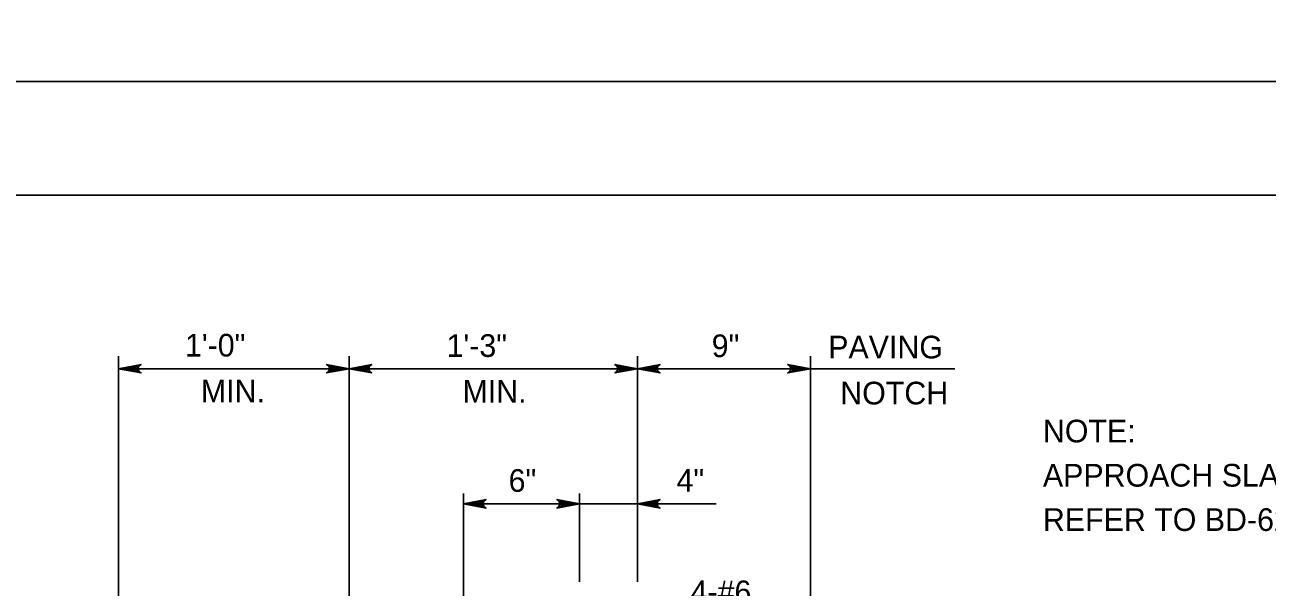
# Model space of a CAD drawing. Extents: x 638653 to 642302, y 298557 to 300414.
# Drawn here: x 639135.8 to 639300, y 299083.7 to 299158 of the extents above; entities that cross this region are included whole.
import ezdxf

# ---------------------------------------------------------------- set-up
doc = ezdxf.new("R2010")
doc.units = 0
doc.layers.add('1', color=7, linetype='Continuous')
doc.layers.add('PLT-BNDY', color=7, linetype='Continuous')

msp = doc.modelspace()

# ---------------------------------------------------------------- linework, layer by layer
at = {"layer": '1'}
for p, q in [((639022.16, 299135.52), (639808.16, 299135.52)), ((639148.15, 299114.21), (639148.15, 299061.56)), ((639178.63, 299114.21), (639178.63, 299074.17)), ((639216.73, 299084.38), (639216.73, 299114.21)), ((639239.59, 299061.62), (639239.59, 299114.21)), ((639148.15, 299112.55), (639178.63, 299112.55)), ((639178.63, 299112.55), (639216.73, 299112.55)), ((639216.73, 299112.55), (639258.67, 299112.55)), ((639193.76, 299061.56), (639193.76, 299096.07)), ((639209.07, 299084.38), (639209.07, 299096.07)), ((639193.76, 299094.69), (639227.16, 299094.69))]:
    msp.add_line(p, q, dxfattribs=at)
for points in [[(639148.15, 299112.55), (639151.14, 299113.11), (639151.02, 299113.03), (639150.91, 299112.95), (639150.85, 299112.85), (639150.79, 299112.75), (639150.77, 299112.65), (639150.75, 299112.55), (639150.77, 299112.45), (639150.79, 299112.35), (639150.85, 299112.25), (639150.91, 299112.15), (639151.02, 299112.07), (639151.14, 299111.99), (639148.15, 299112.55), (639151.02, 299112.07), (639150.91, 299112.15), (639148.15, 299112.55), (639150.85, 299112.25), (639150.79, 299112.35), (639148.15, 299112.55), (639150.77, 299112.45), (639150.75, 299112.55), (639148.15, 299112.55), (639150.77, 299112.65), (639150.79, 299112.75), (639148.15, 299112.55), (639150.85, 299112.85), (639150.91, 299112.95), (639148.15, 299112.55), (639151.02, 299113.03)], [(639178.63, 299112.55), (639175.65, 299111.99), (639175.77, 299112.07), (639175.88, 299112.15), (639175.94, 299112.25), (639176, 299112.35), (639176.02, 299112.45), (639176.03, 299112.55), (639176.02, 299112.65), (639176, 299112.75), (639175.94, 299112.85), (639175.88, 299112.95), (639175.77, 299113.03), (639175.65, 299113.11), (639178.63, 299112.55), (639175.77, 299113.03), (639175.88, 299112.95), (639178.63, 299112.55), (639175.94, 299112.85), (639176, 299112.75), (639178.63, 299112.55), (639176.02, 299112.65), (639176.03, 299112.55), (639178.63, 299112.55), (639176.02, 299112.45), (639176, 299112.35), (639178.63, 299112.55), (639175.94, 299112.25), (639175.88, 299112.15), (639178.63, 299112.55), (639175.77, 299112.07)], [(639178.63, 299112.55), (639181.62, 299113.11), (639181.39, 299112.95), (639181.27, 299112.75), (639181.23, 299112.55), (639181.27, 299112.35), (639181.39, 299112.15), (639181.62, 299111.99), (639178.63, 299112.55), (639181.39, 299112.15), (639181.27, 299112.35), (639178.63, 299112.55), (639181.23, 299112.55), (639181.27, 299112.75), (639178.63, 299112.55), (639181.39, 299112.95)], [(639216.73, 299112.55), (639213.75, 299111.99), (639213.98, 299112.15), (639214.1, 299112.35), (639214.13, 299112.55), (639214.1, 299112.75), (639213.98, 299112.95), (639213.75, 299113.11), (639216.73, 299112.55), (639213.98, 299112.95), (639214.1, 299112.75), (639216.73, 299112.55), (639214.13, 299112.55), (639214.1, 299112.35), (639216.73, 299112.55), (639213.98, 299112.15)], [(639216.73, 299112.55), (639219.72, 299113.11), (639219.49, 299112.95), (639219.37, 299112.75), (639219.33, 299112.55), (639219.37, 299112.35), (639219.49, 299112.15), (639219.72, 299111.99), (639216.73, 299112.55), (639219.49, 299112.15), (639219.37, 299112.35), (639216.73, 299112.55), (639219.33, 299112.55), (639219.37, 299112.75), (639216.73, 299112.55), (639219.49, 299112.95)], [(639239.59, 299112.55), (639236.61, 299111.99), (639236.84, 299112.15), (639236.96, 299112.35), (639236.99, 299112.55), (639236.96, 299112.75), (639236.84, 299112.95), (639236.61, 299113.11), (639239.59, 299112.55), (639236.84, 299112.95), (639236.96, 299112.75), (639239.59, 299112.55), (639236.99, 299112.55), (639236.96, 299112.35), (639239.59, 299112.55), (639236.84, 299112.15)], [(639193.76, 299094.69), (639196.74, 299095.25), (639196.63, 299095.17), (639196.51, 299095.09), (639196.45, 299094.99), (639196.39, 299094.89), (639196.38, 299094.79), (639196.36, 299094.69), (639196.38, 299094.59), (639196.39, 299094.49), (639196.45, 299094.39), (639196.51, 299094.29), (639196.63, 299094.21), (639196.74, 299094.13), (639193.76, 299094.69), (639196.63, 299094.21), (639196.51, 299094.29), (639193.76, 299094.69), (639196.45, 299094.39), (639196.39, 299094.49), (639193.76, 299094.69), (639196.38, 299094.59), (639196.36, 299094.69), (639193.76, 299094.69), (639196.38, 299094.79), (639196.39, 299094.89), (639193.76, 299094.69), (639196.45, 299094.99), (639196.51, 299095.09), (639193.76, 299094.69), (639196.63, 299095.17)], [(639209.07, 299094.69), (639206.09, 299094.13), (639206.32, 299094.29), (639206.44, 299094.49), (639206.47, 299094.69), (639206.44, 299094.89), (639206.32, 299095.09), (639206.09, 299095.25), (639209.07, 299094.69), (639206.32, 299095.09), (639206.44, 299094.89), (639209.07, 299094.69), (639206.47, 299094.69), (639206.44, 299094.49), (639209.07, 299094.69), (639206.32, 299094.29)], [(639216.73, 299094.69), (639219.72, 299095.25), (639219.6, 299095.17), (639219.49, 299095.09), (639219.43, 299094.99), (639219.37, 299094.89), (639219.35, 299094.79), (639219.33, 299094.69), (639219.35, 299094.59), (639219.37, 299094.49), (639219.43, 299094.39), (639219.49, 299094.29), (639219.6, 299094.21), (639219.72, 299094.13), (639216.73, 299094.69), (639219.6, 299094.21), (639219.49, 299094.29), (639216.73, 299094.69), (639219.43, 299094.39), (639219.37, 299094.49), (639216.73, 299094.69), (639219.35, 299094.59), (639219.33, 299094.69), (639216.73, 299094.69), (639219.35, 299094.79), (639219.37, 299094.89), (639216.73, 299094.69), (639219.43, 299094.99), (639219.49, 299095.09), (639216.73, 299094.69), (639219.6, 299095.17)]]:
    msp.add_lwpolyline(points, dxfattribs=at)
at = {"layer": 'PLT-BNDY'}
for points in [[(638982.16, 299744.52), (639823.16, 299744.52), (639823.16, 299150.52), (638982.16, 299150.52)], [(638982.16, 299150.52), (639823.16, 299150.52), (639823.16, 298556.52), (638982.16, 298556.52)]]:
    msp.add_lwpolyline(points, close=True, dxfattribs=at)

# ---------------------------------------------------------------- texts
at = {"layer": '1'}
for s, p in [('1\'-0"', (639156.94, 299114.16)), ('1\'-3"', (639191.51, 299114.11)), ('9"', (639226.55, 299114.08)), ('PAVING', (639241.95, 299113.91)), ('MIN.', (639159.04, 299108.09)), ('MIN.', (639193.62, 299108.04)), ('NOTCH', (639243.54, 299107.83)), ('NOTE:', (639270.32, 299102.81)), ('APPROACH SLAB NOT SHOWN,', (639270.32, 299096.96)), ('6"', (639199.71, 299096.27)), ('4"', (639221.9, 299096.3)), ('REFER TO BD-628M.', (639270.32, 299091.1)), ('4-#6', (639223.76, 299081.55))]:
    msp.add_text(s, height=3, dxfattribs=at).set_placement(p)

doc.saveas('drawing.dxf')
